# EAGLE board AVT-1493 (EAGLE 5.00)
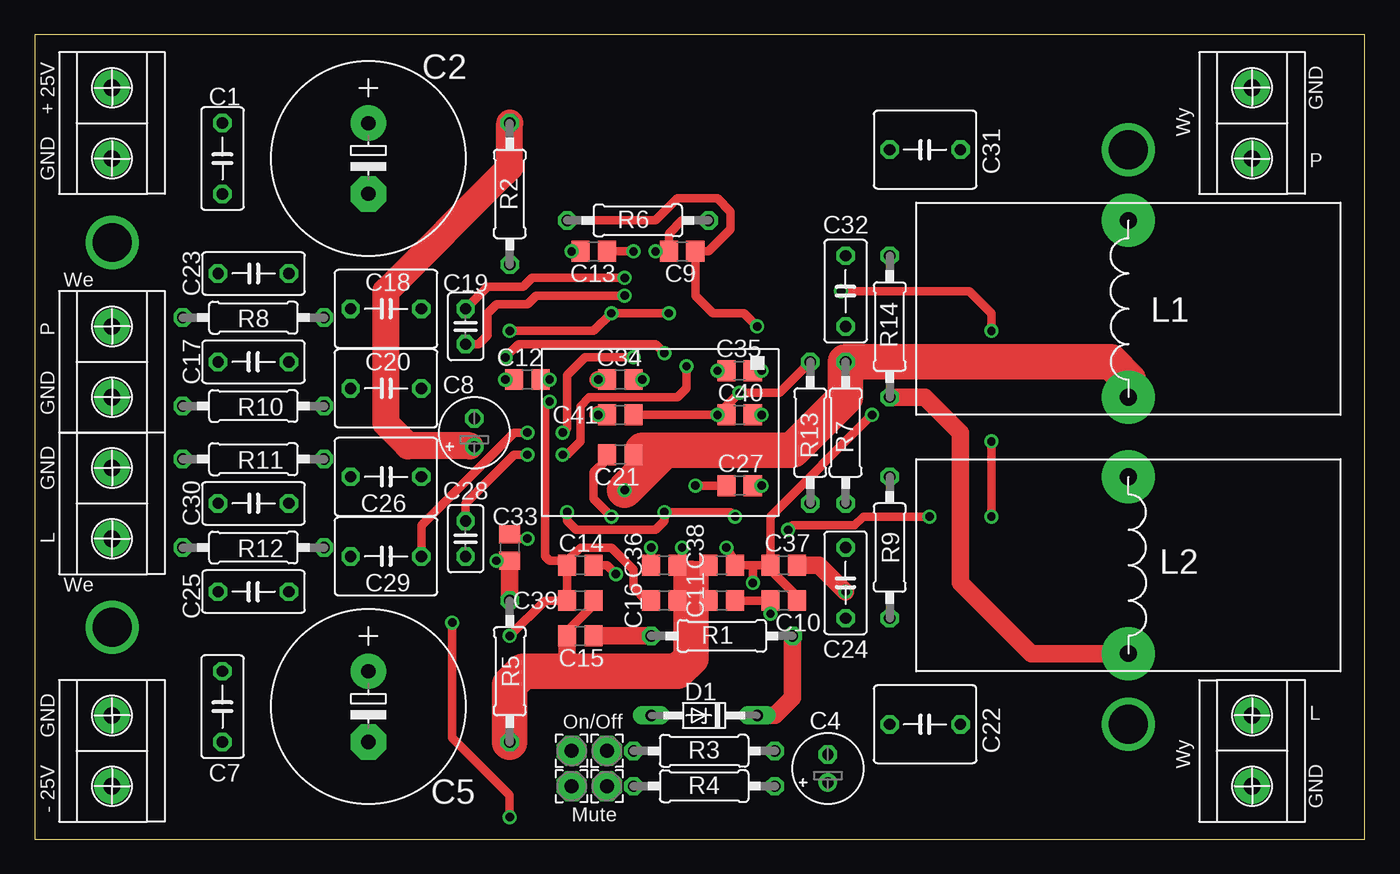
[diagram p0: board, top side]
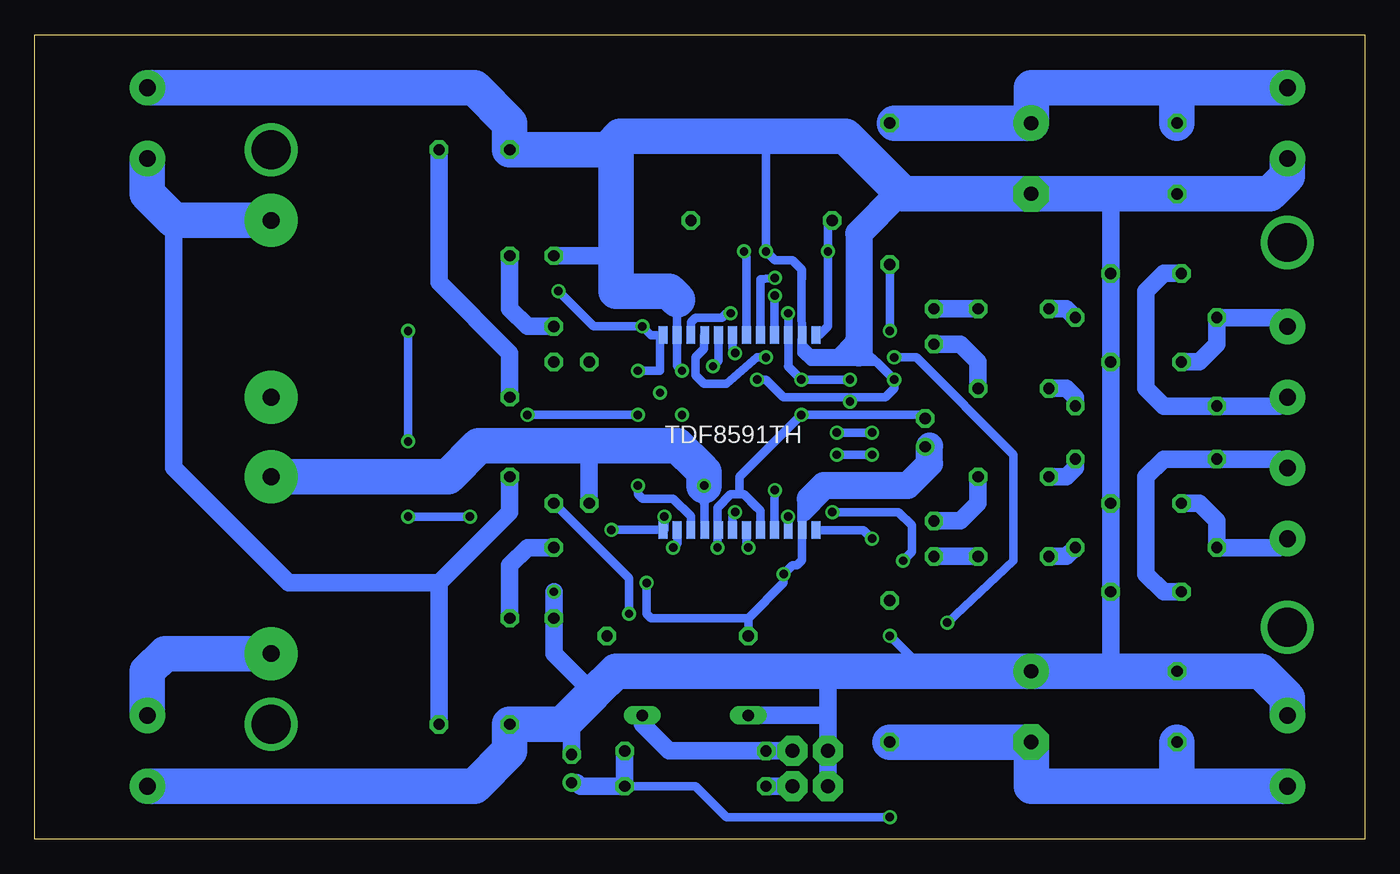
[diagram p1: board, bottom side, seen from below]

Size 95.55 x 57.77 mm. Coordinates in mm from the lower left corner, seen from the top.
Outline: 0,0 95.55,0 95.55,57.77 0,57.77 0,0
Copper layers (1*16): Top 0.035mm / dielectric 1.5mm / Bottom 0.035mm
Design rules "default": minimum track width 10mil, minimum drill 24mil, track to track 8mil, track to pad 8mil, pad to pad 8mil, via to via 8mil, smd to smd 8mil, copper to edge 40mil, drill to drill 8mil, minimum pad ring 10mil, minimum via ring 8mil, stop-mask expansion 4mil, vias tented up to drill 0mil, thermal gap 10mil

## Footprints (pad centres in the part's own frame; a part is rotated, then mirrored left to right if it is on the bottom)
C050-030X075 = drill 0.813 octagon: 1 -2.54,0; 2 2.54,0
E5-13 = drill 1.016 pad 2.54 round: + -2.54,0 | drill 1.016 pad 2.54 octagon: - 2.54,0
E2-5 = drill 0.813 pad 1.27 round: + -1.016,0 | drill 0.813 pad 1.27 octagon: - 1.016,0
C0805 = smd 1.3 x 1.5: 1 -0.95,0; 2 0.95,0
C050-055X075 = drill 0.813 octagon: 1 -2.54,0; 2 2.54,0
C025-025X050 = drill 0.813 octagon: 1 -1.27,0; 2 1.27,0
DO34Z7 = drill 0.813 long: A 3.81,0; C -3.81,0
2,15/1,0 = drill 1.016 pad 2.159 octagon: 1 0,0
0207/10 = drill 0.813 octagon: 1 -5.08,0; 2 5.08,0
ARK2 = drill 1.2 pad 2.54 round: 1 -2.54,0; 3 2.54,0 | drill 0.8 pad 2.54 round: 2 2.54,0
TDF8591TH = smd 0.635 x 1.27 bottom: 1 -5.5,-7; 2 -4.5,-7; 3 -3.5,-7; 4 -2.5,-7; 5 -1.5,-7; 6 -0.5,-7; 7 0.5,-7; 8 1.5,-7; 9 2.5,-7; 10 3.5,-7; 11 4.5,-7; 12 5.5,-7; 13 5.5,7; 14 4.5,7; 15 3.5,7; 16 2.5,7; 17 1.5,7; 18 0.5,7; 19 -0.5,7; 20 -1.5,7; 21 -2.5,7; 22 -3.5,7; 23 -4.5,7; 24 -5.5,7
DLAWIK = drill 1.2 pad 3.81 round: 1 0,6.35; 2 0,-6.35

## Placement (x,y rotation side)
C1  [C050-030X075]  13.49,48.89 270 top
C2  [E5-13]  23.96,48.89 270 top
C4  [E2-5]  56.98,5.07 90 top
C5  [E5-13]  23.96,9.52 270 top
C7  [C050-030X075]  13.49,9.52 270 top
C8  [E2-5]  31.58,29.2 90 top
C9  [C0805]  46.51,42.22 0 top
C10  [C0805]  53.81,17.14 180 top
C11  [C0805]  49.37,17.14 0 top
C12  [C0805]  35.4,33.02 0 top
C13  [C0805]  40.16,42.22 180 top
C14  [C0805]  39.21,19.68 0 top
C15  [C0805]  39.21,14.6 180 top
C16  [C0805]  45.24,17.14 180 top
C17  [C050-030X075]  15.71,34.28 180 top
C18  [C050-055X075]  25.23,38.09 0 top
C19  [C025-025X050]  30.95,36.82 270 top
C20  [C050-055X075]  25.23,32.38 0 top
C21  [C0805]  42.06,27.62 0 top
C22  [C050-055X075]  63.97,8.25 180 top
C23  [C050-030X075]  15.71,40.63 0 top
C24  [C050-030X075]  58.26,18.41 90 top
C25  [C050-030X075]  15.71,17.77 180 top
C26  [C050-055X075]  25.23,26.03 0 top
C27  [C0805]  50.64,25.39 0 top
C28  [C025-025X050]  30.95,21.59 270 top
C29  [C050-055X075]  25.23,20.31 0 top
C30  [C050-030X075]  15.71,24.12 0 top
C31  [C050-055X075]  63.97,49.52 180 top
C32  [C050-030X075]  58.26,39.36 270 top
C33  [C0805]  34.12,20.95 270 top
C34  [C0805]  42.06,33.02 180 top
C35  [C0805]  50.64,33.65 180 top
C36  [C0805]  45.24,19.68 180 top
C37  [C0805]  53.81,19.68 180 top
C38  [C0805]  49.37,19.68 180 top
C39  [C0805]  39.21,17.14 180 top
C40  [C0805]  50.64,30.48 0 top
C41  [C0805]  42.06,30.48 180 top
D1  [DO34Z7]  48.1,8.88 180 top
PAD1  [2,15/1,0]  41.11,6.34 0 top
PAD3  [2,15/1,0]  38.57,6.34 0 top
PAD4  [2,15/1,0]  38.57,3.8 0 top
PAD5  [2,15/1,0]  41.11,3.8 0 top
R1  [0207/10]  49.37,14.6 180 top
R2  [0207/10]  34.12,46.35 270 top
R3  [0207/10]  48.1,6.34 180 top
R4  [0207/10]  48.1,3.8 180 top
R5  [0207/10]  34.12,12.06 90 top
R6  [0207/10]  43.33,44.45 180 top
R7  [0207/10]  58.26,29.2 270 top
R8  [0207/10]  15.71,37.46 0 top
R9  [0207/10]  61.43,20.95 90 top
R10  [0207/10]  15.71,31.11 0 top
R11  [0207/10]  15.71,27.3 0 top
R12  [0207/10]  15.71,20.95 0 top
R13  [0207/10]  55.72,29.2 270 top
R14  [0207/10]  61.43,36.82 270 top
U$1  ARK2  [ARK2]  5.55,34.28 270 top
U$2  TDF8591TH  [TDF8591TH]  44.92,29.2 180 top
U$3  DLAWIK  [DLAWIK]  78.57,38.09 180 top
U$4  ARK2  [ARK2]  5.55,24.12 270 top
U$5  ARK2  [ARK2]  5.55,6.34 270 top
U$6  ARK2  [ARK2]  5.55,51.43 270 top
U$7  DLAWIK  [DLAWIK]  78.57,19.68 0 top
U$8  ARK2  [ARK2]  87.46,51.43 270 top
U$9  ARK2  [ARK2]  87.46,6.34 90 top

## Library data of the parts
C1 C2 C4 C5 C7-C41 R1-R14 = rcl
D1 = diode
PAD1 PAD3-PAD5 = wirepad
U$1 U$4-U$6 U$8 U$9 = ark2
U$2 = tdf8591th
U$3 U$7 = dlawik

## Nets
GND: C1.2 C2.- C4.- C5.+ C7.1 C12.1 C13.1 C14.1 C16.2 C17.1 C22.2 C23.2 C24.1 C25.1 C30.2 C31.2 C32.1 C34.1 C35.2 C37.1 C39.2 D1.A PAD3.1 PAD4.1 U$2.2 U$2.11 U$5.1 U$6.2 U$8.1 U$9.1
N$1: C26.2 C28.1 U$2.5
N$2: C28.2 C29.2 U$2.4
N$3: C18.2 C19.1 U$2.8
N$4: C19.2 C20.2 U$2.9
N$6: C18.1 R8.2
N$7: C20.1 R10.2
N$8: C29.1 R12.2
N$9: C26.1 R11.2
N$10: C23.1 R10.1 U$1.2
N$11: C25.2 R11.1 U$4.1
N$12: C17.2 R8.1 U$1.1
N$13: C30.1 R12.1 U$4.2
N$14: C4.+ R3.1 R4.1 U$2.6
N$15: C10.2 C11.2 R7.2
N$16: C21.1 U$2.15
N$17: C33.1 U$2.13
N$18: D1.C PAD1.1 R1.1 R3.2
N$19: PAD5.1 R4.2
N$20: C40.1 C41.1 R13.1
N$21: C22.1 R9.2 U$3.2 U$8.2
N$22: C31.1 R14.2 U$7.2 U$9.2
N$23: C36.2 U$2.18
N$24: C9.1 R6.1 U$2.7
N$25: C24.2 R9.1
N$26: C21.2 R7.1 U$2.16 U$3.1
N$28: C27.2 U$2.22
N$29: C32.2 R14.1
N$33: C5.- C7.2 C8.- C11.1 C15.2 C16.1 C36.1 C38.2 C39.1 C41.2 R5.1 U$2.17 U$2.20 U$5.2
N$34: C1.1 C2.+ C8.+ C10.1 C14.2 C15.1 C37.2 C38.1 C40.2 R1.2 R2.1 U$2.14 U$2.23 U$6.1
N$35: C27.1 R13.2 U$2.21 U$7.1
VCC: C12.2 C34.2 R2.2 U$2.3 U$2.10
VDD: C9.2 C13.2 C33.2 C35.1 R5.2 R6.2 U$2.1 U$2.12 U$2.19 U$2.24

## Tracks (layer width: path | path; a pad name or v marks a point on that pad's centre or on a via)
GND  (via drill 0.6)
  Top 0.61: 37.94,19.68 C14.1 38.26,19.99 38.25,20 | 37.94,19.68 38.26,19.36 C39.2 36.66,17.14 v34.12,14.6 | 37.94,19.68 C14.1 38.57,20 38.57,20.31 | 38.57,20.31 39.21,20.95 41.43,20.95 43.02,19.36 43.02,18.09 43.97,17.14 C16.2 | 38.25,20 38.57,20.31 | 38.25,20 36.98,20 36.66,20.31 36.66,31.43 v36.98,31.43 | v33.81,33.02 C12.1 | v43.02,42.22 C13.1 | v43.65,33.02 C34.1 | v49.05,33.65 C35.2
  Top 1.27: v58.26,17.77 56.35,19.68 C37.1
  Bottom 0.61: v34.12,14.6 32.22,12.69 | 40.48,40.95 40.48,38.09 U$2.11 40.42,35.5 39.84,34.92 | 40.48,40.95 40.42,40.9 40.42,40.26 | v43.02,42.22 v43.01,42.22 | 49.37,38.09 49.42,38.04 U$2.2 49.42,34.02 v49.05,33.65 | 39.84,34.92 39.21,34.28 37.94,34.28 | C2.- 32.86,46.35 | v43.02,42.22 43.02,49.84 53.49,49.84 53.49,40.32 53.81,40 50.64,40 49.37,38.73 | 36.35,34.92 36.19,34.76 | 36.19,34.76 36.03,34.6 35.71,34.6 36.03,34.28 37.3,34.28 | 37.62,34.6 37.94,34.28 | 36.66,35.55 37.62,34.6 | 36.35,35.87 36.66,35.55 | 37.94,34.92 36.98,34.92 36.66,35.24 36.66,35.55 | 37.94,34.92 39.84,34.92 | 39.84,34.92 39.52,34.6 37.62,34.6 | 37.62,34.6 37.3,34.6 37.62,34.28 39.84,34.28 40.48,34.92 40.48,35.87 | 39.84,34.92 40.16,34.92 | 36.66,35.55 36.98,35.87 37.94,34.92 | 37.94,34.28 37.3,34.28 | 36.19,34.76 35.71,34.92 35.08,34.28 | 36.19,34.76 | 37.3,34.28 35.08,34.28 | 36.98,31.74 34.44,31.74 33.81,32.38 v33.81,33.02 35.08,34.28 | 36.98,31.74 v36.98,31.43 | 40.48,40.95 41.11,41.59 42.38,41.59 v43.02,42.22 | 36.98,31.74 41.75,31.74 C34.1 v43.65,33.02 | 49.52,38.89
  Bottom 1.27: 49.37,38.73 49.37,38.09 | 18.25,46.35 C23.2 C17.1 C30.2 C25.1 18.25,12.06 | 56.98,8.88 C4.- | PAD4.1 PAD3.1 38.57,8.88 | 38.57,12.06 38.57,8.88 | 38.57,8.88 D1.A | 55.08,10.15 55.4,10.47 58.26,13.33 C24.1 v58.26,17.77 | 53.81,41.91 C32.1
  Bottom 1.93: 36.35,34.92 36.35,35.87 36.35,43.49 33.49,46.35 32.86,46.35
  Bottom 2.54: 49.37,38.73 49.52,38.89 50,39.36 53.81,39.36 53.81,40 53.81,41.91 53.81,49.52 54.13,49.52 | U$5.1 5.55,10.15 7.45,12.06 C7.1 18.25,12.06 C5.+ 38.57,12.06 53.81,12.06 55.4,10.47 56.98,8.88 57.62,8.25 C22.2 61.43,6.34 63.97,3.8 U$9.1 | U$6.2 5.55,47.62 6.82,46.35 C1.2 18.25,46.35 24.92,46.35 | 24.92,46.35 C2.- | U$8.1 63.97,53.97 61.43,51.43 C31.2 54.13,49.52 | 54.13,49.52 54.13,49.84 53.49,50.48 37.3,50.48 33.17,46.35 32.86,46.35 24.92,46.35
N$1  (via drill 0.6)
  Top 0.61: v46.83,33.97 46.83,32.38 46.19,31.74 39.84,31.74 39.21,31.11 39.21,28.57 38.25,27.62 v37.94,27.62 | v35.4,27.62 34.44,27.62 30.95,24.12 C28.1
  Bottom 0.61: U$2.5 46.42,34.37 v46.83,33.97 | v35.4,27.62 v37.94,27.62
  Bottom 1.27: C26.2 27.78,24.12 29.04,22.85 C28.1
N$2  (via drill 0.6)
  Top 0.61: v35.4,29.2 34.44,29.2 27.78,22.54 C29.2 | v37.94,29.2 38.25,29.52 38.25,33.33 39.52,34.6 v43.02,34.6
  Bottom 0.61: v35.4,29.2 v37.94,29.2 | U$2.4 47.45,36.2 47.46,36.19 47.46,35.24 48.1,34.6 48.1,33.33 47.46,32.7 45.87,32.7 43.65,34.6 v43.02,34.6
  Bottom 1.27: C29.2 C28.2
N$3  (via drill 0.6)
  Top 0.61: v42.38,40.32 35.71,40.32 35.08,39.68 32.54,39.68 C19.1
  Bottom 0.61: U$2.8 43.42,40.23 v42.38,40.32
  Bottom 1.27: C18.2 C19.1
N$4  (via drill 0.6)
  Top 0.61: v42.38,39.05 36.03,39.05 35.4,38.41 33.17,38.41 32.54,37.78 32.54,36.19 31.9,35.55 C19.2
  Bottom 0.61: U$2.9 42.42,38.69 v42.38,39.05
  Bottom 1.27: C20.2 27.78,34.28 29.04,35.55 C19.2
N$6
  Bottom 1.27: R8.2 21.43,38.09 C18.1
N$7
  Bottom 1.27: R10.2 20.79,31.74 21.43,32.38 C20.1
N$8
  Bottom 1.27: R12.2 21.43,20.31 C29.1
N$9
  Bottom 1.27: R11.2 20.79,26.66 21.43,26.03 C26.1
N$10
  Bottom 1.27: U$1.2 6.18,31.11 R10.1 14.44,31.11 15.71,32.38 15.71,39.36 14.44,40.63 C23.1
N$11
  Bottom 1.27: U$4.1 6.18,27.3 R11.1 14.44,27.3 15.71,26.03 15.71,19.05 14.44,17.77 C25.2
N$12
  Bottom 1.27: U$1.1 6.18,37.46 R8.1 10.63,35.55 11.9,34.28 C17.2
N$13
  Bottom 1.27: U$4.2 6.18,20.95 R12.1 10.63,22.85 11.9,24.12 C30.1
N$14  (via drill 0.6)
  Top 0.61: v30,15.55 30,7.3 34.12,3.17 v34.12,1.58 | v45.24,34.92 44.6,35.55 34.76,35.55 v33.81,34.6
  Bottom 0.61: v30,15.55 25.23,20 25.23,27.62 32.22,34.6 v33.81,34.6 | v34.12,1.58 45.87,1.58 48.1,3.8 R4.1 | U$2.6 45.42,35.1 v45.24,34.92
  Bottom 1.27: C4.+ 56.6,4.06 56.35,3.8 R4.1 R3.1
N$15  (via drill 0.6)
  Top 0.61: 53.18,17.14 C10.2 v52.86,16.19 52.86,16.82 52.54,17.14 C11.2
  Bottom 0.61: v52.86,16.19 52.86,18.73 R7.2
N$16  (via drill 0.6)
  Top 0.61: v41.43,23.17 40.16,24.44 40.16,26.35 41.11,27.3 C21.1
  Bottom 0.61: U$2.15 41.42,22.85 41.43,22.85 v41.43,23.17
N$17  (via drill 0.6)
  Top 0.61: C33.1 34.12,21.59 v35.4,21.59
  Bottom 0.61: U$2.13 36.02,22.2 v35.4,21.59
N$18
  Top 1.27: D1.C 53.18,8.88 54.45,10.15 R1.1
  Bottom 1.27: PAD1.1 R3.2 50,6.34 51.91,8.25 D1.C
N$19
  Bottom 1.27: PAD5.1 R4.2
N$20  (via drill 0.6)
  Top 0.61: R13.1 53.49,32.06 v50.64,32.06 49.37,30.79 | 49.37,30.79 C40.1 | 49.37,30.79 v49.05,30.48 C41.1
N$21
  Bottom 1.27: R9.2 61.43,23.49 66.51,18.41 | C22.1 66.51,18.41 | 85.56,44.45 85.56,26.66 77.3,18.41 66.51,18.41
  Bottom 2.54: U$3.2 85.56,44.45 87.46,46.35 U$8.2
N$22
  Top 1.27: U$7.2 71.59,13.33 66.51,18.41 66.51,29.2 63.97,31.74 R14.2
  Bottom 1.27: R14.2 61.43,34.92 66.51,40 C31.1
  Bottom 2.54: U$9.2 87.46,12.06 86.19,13.33 U$7.2
N$23  (via drill 0.6)
  Top 0.61: 44.29,19.36 C36.2 v44.29,20.95
  Bottom 0.61: U$2.18 44.42,21.09 v44.29,20.95
N$24  (via drill 0.6)
  Top 0.61: v44.6,42.22 C9.1 45.55,43.49 46.51,44.45 R6.1
  Bottom 0.61: U$2.7 44.42,41.72 v44.6,42.22
N$25
  Bottom 1.27: R9.1 61.43,19.68 60.16,20.95 C24.2
N$26  (via drill 0.6)
  Top 0.406: 43.65,27.93 C21.2
  Top 2.54: U$3.1 78.57,33.02 77.3,34.28 R7.1 58.26,31.74 54.45,27.93 45.24,27.93 | 43.97,27.93 43.65,27.93 | 45.24,27.93 43.97,27.93 | 43.97,27.93 43.97,26.66 v42.38,25.08 45.24,27.93
  Bottom 0.61: U$2.16 42.42,24.09 v42.38,25.08
N$28  (via drill 0.6)
  Top 0.61: v52.22,25.39 C27.2
  Bottom 0.61: U$2.22 48.42,23.18 49.68,24.44 51.91,24.44 52.22,24.76 v52.22,25.39
N$29
  Bottom 1.27: R14.1 61.43,38.09 60.16,36.82 C32.2
N$31  (via drill 2.8 pad 3.81)
  other vias: 78.57,49.52 5.55,42.86 5.55,15.23
N$32  (via drill 2.8 pad 3.81)
  other vias: 78.57,8.25
N$33  (via drill 0.6)
  Top 0.61: C15.2 38.26,14.92 40.16,16.82 C39.1 | C16.1 C11.1 48.41,17.45 47.14,18.73 | 47.14,18.73 C36.1 | C38.2 | 47.14,18.73 47.46,18.73 C38.2 | C38.2 48.41,20 | C36.1 C38.2 | C36.1 | v46.51,20.95 46.51,20 C36.1
  Top 1.27: 38.25,14.28 C15.2 38.25,12.06 | v40.48,30.48 C41.2
  Top 2.54: R5.1 34.12,11.11 35.08,12.06 38.25,12.06 46.19,12.06 47.14,13.01 47.14,18.73
  Bottom 0.61: C8.- 31.58,30.16 31.9,30.48 v40.48,30.48 41.43,29.52 44.92,26.03 44.92,24.76 | U$2.17 43.42,23.58 44.6,24.76 | U$2.20 46.42,22.45 46.51,22.54 46.51,23.17 | 44.92,24.76 45.55,24.76 46.51,23.81 46.51,23.17 | 44.92,24.76 44.6,24.76 | 44.6,24.76 43.65,23.81 | v46.51,20.95 46.51,23.17
  Bottom 1.27: C5.- R5.1
  Bottom 2.54: U$5.2 13.49,3.8 | 13.49,3.8 23.96,3.8 C5.- R5.1 | 13.49,3.8 C7.2
N$34  (via drill 0.6)
  Top 0.254: 33.81,47.94 34.12,47.62
  Top 0.61: v49.68,20.95 50.32,20 C38.1 51.59,19.68 | v41.75,19.05 41.11,19.68 C14.2 | C37.2 53.18,19.68 | 51.59,19.68 C37.2 | v51.59,18.41 51.59,19.68 | C37.2 52.86,19.36 54.76,17.46 C10.1 | C8.+ 31.58,28.25 31.27,28.25 | C37.2 | v60.16,30.48 52.86,23.17 C37.2 | v52.22,30.48 C40.2
  Top 1.27: C15.1 R1.2
  Top 1.93: R2.1 34.12,48.25 33.81,47.94 25.23,39.36 25.23,29.84 26.82,28.25 31.27,28.25
  Bottom 0.61: 39.84,24.12 39.52,24.44 38.89,24.44 38.57,24.76 | U$2.23 49.38,22.2 49.37,22.22 49.37,21.27 v49.68,20.95 | R1.2 44.29,15.87 | 44.29,15.87 41.75,18.41 v41.75,19.05 41.11,19.68 40.79,19.68 40.42,20.05 U$2.14 40.42,23.55 39.84,24.12 | 44.29,15.87 51.27,15.87 51.59,16.19 v51.59,18.41 | 38.57,24.76 33.49,24.76 32.86,25.39 31.58,26.66 C8.+ 31.58,28.25 | v60.16,30.48 v52.22,30.48 | 38.57,24.76 39.21,24.76 39.84,24.12 | 39.84,24.12 40.48,23.49 | 40.48,23.49 40.48,23.17 | 40.48,23.17 40.48,22.85 | 40.48,23.49 40.48,24.44 | 40.48,23.17 40.16,23.17 38.57,24.76
  Bottom 1.27: R2.1 33.81,51.43
  Bottom 1.93: 31.27,28.25 31.27,26.98 32.86,25.39 37.3,25.39 | 37.3,25.39 37.94,25.39 | 37.3,25.39 38.89,25.39 39.84,24.44
  Bottom 2.54: 13.49,53.97 U$6.1 | 13.49,53.97 23.96,53.97 C2.+ 33.81,51.43 | 13.49,53.97 C1.1
N$35  (via drill 0.6)
  Top 0.61: 48.1,25.39 v47.46,25.39 C27.1
  Bottom 0.61: U$2.21 47.42,24.09 47.46,24.12 v47.46,25.39 | 47.78,25.71 | v47.46,25.39 47.46,26.03 47.78,26.35 | 47.78,26.35 48.1,26.66 47.78,26.66 47.78,26.35 | 47.78,25.71 47.78,26.35 | v47.46,25.39 47.78,25.71
  Bottom 1.27: 55.72,28.25 R13.2
  Bottom 2.54: U$7.1 65.88,26.03 63.65,28.25 56.03,28.25 | 56.03,28.25 55.72,28.25 | v47.46,25.39 47.46,26.35 47.78,26.66 49.37,28.25 56.03,28.25
VCC  (via drill 0.6)
  Top 0.61: v45.55,37.78 v41.43,37.78 40.16,36.51 v34.12,36.51 | C12.2 v36.98,33.02
  Top 1.27: v40.48,33.02 C34.2
  Bottom 0.61: v41.43,37.78 41.42,37.45 U$2.10 41.42,33.96 41.44,33.96 41.11,33.65 v40.48,33.02 v36.98,33.02 | U$2.3 48.41,37.14 48.1,37.46 46.19,37.46 45.87,37.78 v45.55,37.78 | v34.12,36.51 R2.2
VDD  (via drill 0.6)
  Top 0.254: v52.22,33.65 C35.1
  Top 0.61: v51.91,36.82 50.95,37.78 48.73,37.78 47.46,39.05 C9.2 48.41,42.22 50,43.81 50,45.08 49.05,46.03 46.19,46.03 44.6,44.45 R6.2 | v50.32,23.17 50,23.49 v45.24,23.49 45.24,22.85 44.6,22.22 38.89,22.22 38.25,22.85 v38.25,23.49 | C33.2 v33.17,20 | v68.73,23.17 v68.73,28.57 | v64.29,23.17 59.52,23.17 58.89,22.54 54.45,22.54 v54.13,22.22 | v68.73,36.51 68.73,37.78 67.14,39.36 v57.94,39.36 | v38.57,42.22 C13.2
  Top 1.27: R5.2 C33.2
  Bottom 0.61: 51.27,36.19 U$2.1 50.62,36.2 50.64,36.19 | 38.57,44.13 38.57,44.45 R6.2 | 38.57,44.13 38.57,44.45 | 38.57,44.13 v38.57,42.22 38.57,36.82 39.21,36.19 39.22,36.2 U$2.12 | v50.32,23.17 50.32,22.22 50.33,22.2 U$2.24 50.62,22.2 50.64,22.22 v54.13,22.22 | U$2.19 45.42,23.35 v45.24,23.49 | v38.25,23.49 33.49,23.49 32.54,22.54 32.54,20.63 v33.17,20 | v52.22,33.65 50.64,33.65 50.64,36.19 | 51.27,36.19 50.64,36.19 | 51.27,36.19 v51.91,36.82 55.4,36.82 v57.94,39.36 | v68.73,28.57 v68.73,36.51 | v64.29,23.17 v68.73,23.17

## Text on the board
tPlace: GND | + 25V | Wy | P | GND | We | L1 | P | GND | GND | L | L2 | We | L | GND | On/Off | Wy | GND | - 25V | Mute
